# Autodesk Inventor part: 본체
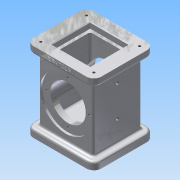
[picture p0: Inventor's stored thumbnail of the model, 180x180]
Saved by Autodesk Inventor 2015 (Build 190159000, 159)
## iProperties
Created: 2017-08
Part Number: 본체
Material: 알루미늄 6061
Document SubType Name: Modeling
Designer: Administrator
Density: 2.7 g/cm^3
Appearance: 알루미늄 - 평지
Author: Administrator
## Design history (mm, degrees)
sketch "스케치1"
  geometry: L1 (37, -33)-(-37, -33); L2 (-37, -33)-(-37, 33); L3 (-37, 33)-(37, 33); L4 (37, 33)-(37, -33); 1 further point
  constraints: 8 end point, 2 parallel, 1 horizontal, 1 perpendicular
  dimensions: "d0" = 37 distance from line of point (0, 0) L4; "d1" = 74 distance between parallel lines of L2 L4; "d2" = 66 distance between parallel lines of L3 L1; "d3" = 33 distance from line of point (0, 0) L1
extrude "돌출1" new body sketch "스케치1" distance "d4" = 108; taper "d5" = 0 deg
sketch "스케치2"
  geometry: L1 (-46, 41)-(46, 41); L2 (46, 41)-(46, -41); L3 (46, -41)-(-46, -41); L4 (-46, -41)-(-46, 41); 1 further point
  constraints: 8 end point, 2 parallel, 1 horizontal, 1 perpendicular
  dimensions: "d6" = 46 distance from line of point (0, 0) L4; "d7" = 92 distance between parallel lines of L2 L4; "d8" = 41 distance from line of point (0, 0) L1; "d9" = 82 distance between parallel lines of L3 L1
extrude "돌출2" join sketch "스케치2" distance "d10" = 10; taper "d11" = 0 deg
node "작업 평면1"
sketch "스케치3"
  geometry: L1 (-26, -26)-(26, -26); L2 (26, -26)-(26, 26); L3 (26, 26)-(-26, 26); L4 (-26, 26)-(-26, -26); L5 (-26, -26)-(26, 26); L6 (26, -26)-(-26, 26); 1 further point
  constraints: 12 end point, 2 midpoint, 2 parallel, 1 horizontal, 1 perpendicular
  dimensions: "d12" = 52 distance of L2.end L3.end; "d13" = 52 distance between parallel lines of L1 L3
extrude "돌출3" cut sketch "스케치3" distance "d14" = 8; taper "d15" = 0 deg
sketch "스케치4"
  geometry: L1 (22, -22)-(-22, -22); L2 (-22, -22)-(-22, 22); L3 (-22, 22)-(22, 22); L4 (22, 22)-(22, -22); L5 (22, -22)-(-22, 22); L6 (-22, -22)-(22, 22); 1 further point
  constraints: 12 end point, 2 midpoint, 2 parallel, 1 horizontal, 1 perpendicular
  dimensions: "d16" = 44 distance of L2.end L3.end; "d17" = 44 distance of L1.end L2.end
extrude "돌출4" cut sketch "스케치4" distance "d18" = 74; taper "d19" = 0 deg
sketch "스케치5"
  geometry: L1 (24, -24)-(-24, -24); L2 (-24, -24)-(-24, 24); L3 (-24, 24)-(24, 24); L4 (24, 24)-(24, -24); L5 (24, -24)-(-24, 24); L6 (-24, -24)-(24, 24); 1 further point
  constraints: 12 end point, 2 midpoint, 2 parallel, 1 horizontal, 1 perpendicular
  dimensions: "d20" = 48 distance of L2.end L3.end; "d21" = 48 distance of L3.end L1.start
extrude "돌출5" cut sketch "스케치5" distance "d22" = 16; taper "d23" = 0 deg
sketch "스케치6"
  geometry: L1 (83, -98)-(-9, -98) reference; C1 r 35 at (37, -44); 2 further points
  constraints: 1 centre point, 1 midpoint, 1 vertical alignment
  dimensions: "d24" = 70 diameter of C1; "d25" = 54 distance from line of L1 C1.centre
extrude "돌출6" cut sketch "스케치6" distance "d26" = 3; taper "d27" = 0 deg
sketch "스케치7"
  geometry: L1 (46, 54)-(-46, 54) reference; C1 r 24 at (0, 0); 2 further points
  constraints: 1 centre point, 1 midpoint, 1 vertical alignment
  dimensions: "d28" = 48 diameter of C1
extrude "돌출7" cut sketch "스케치7" stored distance "d29" = 3; taper "d30" = 0 deg
sketch "스케치8"
  geometry: L1 (83, 0)-(74, 0) reference; L2 (74, 0)-(0, 0) reference; L3 (0, -88)-(0, 0) reference; L4 (0, -88)-(74, -88) reference; L5 (74, 0)-(74, -88) reference; L6 (83, 10)-(83, 0) reference; L7 (-9, 10)-(83, 10) reference; L8 (-9, 0)-(-9, 10) reference; L9 (0, 0)-(-9, 0) reference; L10 (-9, -88)-(0, -88) reference; L11 (-9, -98)-(-9, -88) reference; L12 (83, -98)-(-9, -98) reference; L13 (83, -88)-(83, -98) reference; L14 (74, -88)-(83, -88) reference; C1 r 24 at (37, -44) reference; C2 r 35 at (37, -44); 1 further point
  constraints: 1 centre point, 1 coincident
  dimensions: "d31" = 70 diameter of C2
extrude "돌출8" cut sketch "스케치8" distance "d32" = 3; taper "d33" = 0 deg
fillet "모깎기1" dims "d34" = 10
fillet "모깎기2" dims "d35" = 3
fillet "모깎기3" dims "d36" = 3
fillet "모깎기4" dims "d37" = 3
fillet "모깎기5" dims "d38" = 3
sketch "스케치9" dims "d39" = 58
  geometry: L1 (36, 54)-(-36, 54) reference; L2 (-37, 41)-(-37, -41) reference; 6 further points
  constraints: 3 midpoint, 3 vertical alignment, 1 horizontal alignment, 2 other
hole "구멍1" sketch "스케치9" at (0, 29) diameter "d40" = 3.242; stored, may be unused: countersink angle "d44" = 90 deg, drill point angle "d46" = 118 deg; dims "d41" = 4, "d42" = 4, "d43" = 2, "d45" = 6
sketch "스케치10"
  geometry: L1 (-46, -31)-(-46, 31) reference; L2 (-36, 41)-(36, 41) reference; L3 (46, 31)-(46, -31) reference; L4 (36, -41)-(-36, -41) reference; L5 (26, -26)-(26, 26) reference; L6 (26, 26)-(-26, 26) reference; L7 (-26, 26)-(-26, -26) reference; L8 (-26, -26)-(26, -26) reference; A1 r 10 centre (-36, -31) between (-46, -31) and (-36, -41) reference; A2 r 10 centre (-36, 31) between (-36, 41) and (-46, 31) reference; A3 r 10 centre (36, 31) between (46, 31) and (36, 41) reference; A4 r 10 centre (36, -31) between (36, -41) and (46, -31) reference; 5 further points
  constraints: 4 coincident
hole "구멍2" sketch "스케치10" at (-36, 31), (-36, -31), (36, -31), (36, 31) diameter "d50" = 3.242; stored, may be unused: countersink angle "d54" = 90 deg, drill point angle "d56" = 118 deg; dims "d51" = 4, "d52" = 4, "d53" = 2, "d55" = 6
sketch "스케치11"
  geometry: L1 (60, 0)-(0, 0) reference; L2 (65.196, -3)-(67.928, -3) reference; L3 (70.95, -6)-(70.95, -13) reference; L4 (70.95, -13)-(62.276, -13) reference; L5 (62.276, -13)-(62.276, -7) reference; L6 (59.724, -7)-(59.724, -13) reference; L7 (59.724, -13)-(0.276, -13) reference; L8 (0.276, -13)-(0.276, -7) reference; L9 (-2.276, -7)-(-2.276, -13) reference; L10 (-2.276, -13)-(-10.95, -13) reference; L11 (-10.95, -13)-(-10.95, -6) reference; L12 (-7.928, -3)-(-5.196, -3) reference; L13 (0, 0)-(0, 82) reference; L14 (-5.196, 85)-(-7.928, 85) reference; L15 (-10.95, 88)-(-10.95, 95) reference; L16 (-10.95, 95)-(-2.276, 95) reference; L17 (-2.276, 95)-(-2.276, 89) reference; L18 (0.276, 89)-(0.276, 95) reference; L19 (0.276, 95)-(59.724, 95) reference; L20 (59.724, 95)-(59.724, 89) reference; L21 (62.276, 89)-(62.276, 95) reference; L22 (62.276, 95)-(70.95, 95) reference; L23 (70.95, 95)-(70.95, 88) reference; L24 (67.928, 85)-(65.196, 85) reference; L25 (60, 0)-(60, 82) reference; L26 (0, 82)-(60, 82) reference; L27 (61, 95)-(-1, 95) reference; L28 (61, -13)-(-1, -13) reference; 5 further points
  constraints: 4 horizontal alignment, 2 midpoint, 2 vertical alignment, 8 other
  dimensions: "d57" = 38 distance from line of point (30, 25) L7; "d58" = 42 distance of point (30, 67) point (30, 25)
hole "구멍3" sketch "스케치11" at (30, 67), (30, 25) diameter "d59" = 4.134; stored, may be unused: countersink angle "d63" = 90 deg, drill point angle "d65" = 118 deg; dims "d60" = 10, "d61" = 4, "d62" = 2, "d64" = 41.2
node "작업 평면2"
sketch "스케치12"
  geometry: L1 (5.36, -14.666)-(66.64, -14.666); L2 (66.64, -14.666)-(66.64, 6.666); L3 (66.64, 6.666)-(5.36, 6.666); L4 (5.36, 6.666)-(5.36, -14.666); L5 (72, -7)-(0, -7) reference; L6 (72, 0)-(72, -7) reference; L7 (72, 0)-(0, 0) reference; L8 (0, -7)-(0, 0) reference; L9 (-10, 0)-(-10, -7) reference; L10 (72, 0)-(82, 0) reference; 4 further points
  constraints: 2 midpoint, 1 horizontal alignment, 1 vertical alignment, 2 other
  dimensions: "d67" = 46 distance from line of point (36, -4) L9; "d68" = 4 distance from line of L10 point (36, -4)
feature "엠보싱1" sketch "스케치12" dims "d0" = 37, "d1" = 74, "d2" = 66, "d3" = 33, "d69" = 0.5, "d70" = 0
chamfer "모따기1" distance "d71" = 1; stored, may be unused: second distance "d72" = 2, angle "d73" = 45 deg
fillet "모깎기6" dims "d74" = 3
fillet "모깎기7" dims "d75" = 3
node "솔리드1"
mirror "대칭1"
pattern_circular "원형 패턴1" dims angle "d48" = 360 deg
mirror "대칭2"
mirror "대칭3"
node "투영된 루프1"
node "절단 모서리 투영1"
node "절단 모서리 투영2"
node "절단 모서리 투영3"
other parameters: "d66" = 2
